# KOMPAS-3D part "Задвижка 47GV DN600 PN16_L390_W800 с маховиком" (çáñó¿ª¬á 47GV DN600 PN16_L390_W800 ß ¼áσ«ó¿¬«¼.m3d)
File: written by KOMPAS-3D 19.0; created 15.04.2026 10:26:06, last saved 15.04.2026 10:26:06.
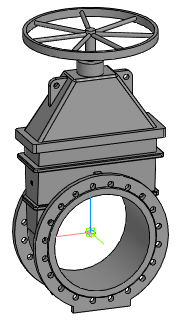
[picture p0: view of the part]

Document properties: Автор: Евгений; Полное имя файла: Z:\3.Личные\kachalov\3d для проектировщиков\2.1 Тип 47GV, 47GV.Z\Задвижка 47GV_DN40-DN600\stp_Задвижка 47GV\Задвижка 47GV DN600 PN16_L390_W800 с маховиком.m3d

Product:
- Part/product: Задвижка 47GV DN600 PN16_L390_W800 с маховиком

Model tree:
1. Операция без истории:1  (labels: Задвижка 47GV DN600 PN16_L390_W800 с маховиком)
